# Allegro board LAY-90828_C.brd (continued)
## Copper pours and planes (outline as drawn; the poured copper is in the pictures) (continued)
DCDC_VDD_CORE on TOP: 72.45,24.83 72.45,22.93 72.58,22.8 74.1,22.8 74.48,22.42 74.48,21.91 74.87,21.53 75.37,21.53 75.63,21.78 75.63,24.2 75.37,24.45 74.23,24.45 73.72,24.96 72.58,24.96
LDO_3V3 on TOP: 43.5,30.29 45.02,30.29 45.15,30.17 45.15,24.32 43.12,22.29 42.73,22.29 42.61,22.42 42.61,24.58 43.12,25.09 43.12,29.91
LDO_3V3 on POWER: 43.5,29.66 43.5,24.58 45.78,22.29 45.78,20.01 49.74,16.05 49.74,10.37 50.12,9.98 52.28,9.98 53.93,11.64 53.93,17.1 54.93,18.1 54.93,20.26 53.66,21.53 51.24,21.53 48.83,23.94 48.83,26.48 45.4,29.91 43.75,29.91
MCU_LINK_3V3 on TOP: 34.61,27.5 34.48,27.37 33.34,27.37 33.21,27.5 33.21,29.79 33.59,30.17 34.48,30.17 34.61,30.04
MCU_LINK_3V3 on BOTTOM: 33.21,26.99 32.96,26.74 31.81,26.74 31.3,27.25 31.3,31.94 30.92,32.33 30.92,33.6 30.8,33.72 30.03,33.72 29.91,33.6 29.91,23.56 30.29,23.18 31.18,23.18 31.43,23.44 31.43,25.34 31.56,25.47 33.72,25.47 34.1,25.85 34.1,28.64 33.97,28.77 33.34,28.77 33.21,28.64
USB_OTG_VBUS on TOP: 4.25,23.94 6.54,23.94 7.05,24.45 7.05,25.72 7.17,25.85 8.83,25.85 8.95,25.72 8.95,22.93 8.7,22.67 7.43,22.67 6.79,23.31 4.25,23.31
N85648 on TOP: 22.92,26.99 21.53,26.99 21.14,26.61 19.24,26.61 19.11,26.48 19.11,25.85 18.86,25.59 15.43,25.59 15.18,25.34 15.18,22.67 15.43,22.42 17.72,22.42 18.1,22.8 18.1,24.83 18.22,24.96 19.11,24.96 20.13,25.98 21.27,25.98 21.91,26.61 22.8,26.61 22.92,26.74
N85830 on TOP: 22.41,25.98 21.65,25.98 21.4,25.72 20.38,25.72 19.37,24.71 18.73,24.71 18.6,24.58 18.6,22.8 18.73,22.67 20,22.67 20.38,23.05 20.38,24.45 21.14,25.21 21.4,25.21 21.91,25.72 22.41,25.72
N17592677 on TOP: 7.17,38.68 6.92,38.42 4.13,38.42 4.13,39.06 6.67,39.06 7.17,39.56 7.17,40.83 7.56,41.22 8.83,41.22 8.95,41.09 8.95,38.93 8.7,38.68

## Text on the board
BOTTOM: 170-90828 REV C | 07 | L4_SS
Board Geometry/Soldermask Bottom: 08 | SECONDARY SOLDERMASK
Ref Des/Silkscreen Bottom: P4_6 | P2_5 | P3_7 | P4_0 | P0_21 | P2_3 | P3_9 | P3_11 | P0_24 | P4_20 | P4_23 | P0_15 | P3_1 | GND | VDD | P4_1 | P4_7 | P3_0 | P2_4 | P3_2 | P2_6 | P3_8 | P4_14 | P0_14 | P0_23 | P4_19 | P0_20 | P3_10 | VREFO | P1_17 | PO_24 | P1_16 | VDDA | NC | P0_25 | P1_1 | P4_13 | P0_22 | P1_2 | P4_21 | P0_26 | RESET | P1_0 | P3_17 | P0_27 | P1_3 | P3_16 | P0_28 | P5V0 | P3_14 | P3_15 | P0_29 | P2_7 | P2_9 | 5-9VIN | P3_12 | P1_7 | P3_18 | P4_15 | P3_6 | P0_18 | p4_16 | P2_8 | P2_0 | P0_16 | P4_17 | P4_2 | P0_17 | P4_12 | P4_3 | P5_7 | P0_19 | P2_1 | P1_12 | P2_11 | P2_10 | P0_5 | P2_2 | P1_10 | P1_8 | P1_6 | P1_4 | P1_18 | P1_14 | P1_13 | P4_4 | P4_5 | P4_18 | P5_3 | P5_6 | P5_2 | P0_4 | PCLK | P1_11 | P1_9 | 3V3 | P1_5 | 5V0 | P5_4 | P1_19 | P5_5 | P1_15 | 09 | SECONDARY SILKSCREEN
User.Comments: 1 OF 1 | TEST PROBE | 1/1 | 1
TOP: 04 | L1_PS
Board Geometry/Soldermask Top: 03 | PRIMARY SOLDERMASK
Ref Des/Silkscreen Top: CAN_L | CAN_H | GND | 3V3 | SDA | PWM | AN | SCL | RST | INT | HS | VS | MCLK | PCLK | CS | RX | SCK | TX | D6 | D7 | MISO | D4 | D5 | MOSI | D3 | D2 | 5V0 | D0 | D1 | PWNN | SOCKET BOARD | mikro | BLK | DC | WR | TE | D9 | D11 | D13 | D15 | RD | D10 | D12 | P3V3 | D8 | D14 | 02 | PRIMARY SILKSCREEN | FRDM-MCXN236 | BUS
GND: 05 | L2_GND
POWER: 06 | L3_POWER
XSECTION_CHART: *  SURFACE - AIR 0 MIL | *  DIELECTRIC - SOLDERMASK 0.7 MIL | L1 TOP CONDUCTOR - 1/2OZ_COPPER_PLATED 2.1 MIL | *  DIELECTRIC - FR-4 4 MIL | L2 GND PLANE - 1OZ_COPPER 1.2 MIL | *  DIELECTRIC - FR-4 45.4 MIL | L3 POWER PLANE - 1OZ_COPPER 1.2 MIL | L4 BOTTOM CONDUCTOR - 1/2OZ_COPPER_PLATED 2.1 MIL | DESIGN CROSS SECTION CHART | ___________________________ | TOTAL THICKNESS 61.4 MIL | 1-4
DIMENSION: SCALE: NONE | BOARD THICKNESS TOLERANCE +/-10% | BLACK | 19 | 16 | DETAIL | LAYER STACKUP | PRIMARY DATUM | GRID ORIGIN | A
DISPLAY_TOP: 01 | PRIMARY PASTEMASK
User.5: 10 | SECONDARY PASTEMASK
User.10: OF 10 | FRDM-MCXN236
User.13: 22. THIS FAB_VIAFILL.ART SHOWS LOCATIONS OF VIA-IN-PAD TO BE FILLED. | 1/1 | 2 | 3 | FAB SUPPLIER: DISREGARD THIS PAGE IF VIA-IN-PAD DOESN'T APPLY OR NOT REQUIRED ON FAB.ART | CAD DESIGNER: DELETE THIS FAB PAGE IF VIAL FILL IS NOT USED ON THIS DESIGN
User.14: 24. | 1/1 | 3 | CAD DESIGNER: DELETE THIS FAB PAGE IF BACKDRILL IS NOT USED ON THIS DESIGN. | FAB SUPPLIER: DISREGARD THIS PAGE IF BACKDRILL REQUIRMENT IS NOT PROVIDED.
User.15: 03-25-24 | 09-13-23 | ZHANG.Y | STEVEN | JUSTIN | C | B | ADD TP(TEST POINT) | UPDATED PER ECO175115
User.19: TOP TO LAYER X | BACK DRILL REFERENCE | BOTTOM TO LAYER X | LAYER X | MUST CUT LAYER | LAYER X+1 | MUST NOT CUT LAYER | LAYER X-1
User.20: FIGURE | FINISHED_SIZE | 8.0 | 10.0 | 16.0 | 28.0 | 40.0 | 41.0 | 44.0 | 47.0 | 125.0 | 55.0x24.0 | 59.0x32.0 | 83.0x24.0 | ROTATION | - | 0.000 | 90.000 | DRILL CHART: TOP to BOTTOM | ALL UNITS ARE IN MILS | TOLERANCE_DRILL | +0.0/-8.0 | +0.0/-10.0 | +2.0/-2.0 | +3.0/-3.0 | TOLERANCE_TRAVEL | PLATED | NON-PLATED | QTY | 69 | 524 | 32 | 10 | 91 | 72 | 16 | 4 | 2 | 8
